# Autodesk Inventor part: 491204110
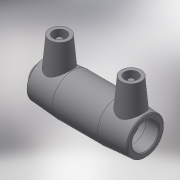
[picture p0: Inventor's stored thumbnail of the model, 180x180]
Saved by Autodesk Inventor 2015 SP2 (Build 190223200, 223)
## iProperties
Created: 2017-06
Part Number: 491204110
Material: Generic
Description: PLASSON END CAP 110
Document SubType Name: Modeling
Designer: KIM
Mass: 38.9236 g
Surface Area: 152.394 cm^2
Volume: 38.9236 cm^3
Density: 1 g/cm^3
Appearance: Default
Author: KIM
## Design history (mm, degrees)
derived "491204.ipt"
feature "Solid1::491204.ipt"
tag "TaggingFeature1"
body "Solid1"
other parameters: "d0" = 163, "d3" = 78, "d4" = 51.5, "d5" = 126, "d6" = 104.5, "d8" = 168 deg, "d10" = 31.2, "d11" = 10.4, "d13" = 164.8, "d14" = 17.6296, "d15" = 78, "d16" = 78, "d17" = 104.5, "d19" = 3.52592, "d20" = 168 deg, "d22" = 131.6, "d24" = 127.652, "d25" = 135 deg, "d26" = 74.16, "d27" = 135 deg, "d29" = 81, "d30" = 15, "d31" = 65.92, "d34" = 5 deg, "d35" = 15, "d39" = 5 deg, "d41" = 4, "d42" = 14, "d43" = 0, "d45" = 4, "d46" = 14, "d47" = 0, "d48" = 206, "d49" = 1, "d51" = 88, "d52" = 3.708, "d53" = 121, "d54" = 3.708, "d56" = 11, "d57" = 3.3, "d60" = 30.9, "d61" = 2.2, "d63" = 206, "d64" = 1, "d66" = 88, "d67" = 22, "d68" = 121, "d69" = 4.12, "d70" = 0, "d71" = 3.708, "d72" = 3, "d73" = 0, "d74" = 22.62, "d75" = 7.54, "d76" = 3, "d77" = 0, "L_" = 206, "L_1" = 78, "A_" = 81, "d_2" = 12, "L_0" = 163, "d55" = 11
